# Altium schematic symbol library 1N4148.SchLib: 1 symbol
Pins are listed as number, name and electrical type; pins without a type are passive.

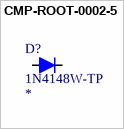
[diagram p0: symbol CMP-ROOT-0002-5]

## CMP-ROOT-0002-5
designator D?, comment 1N4148W-TP
MICRO COMMERCIAL COMPONENTS - 1N4148W-TP - SWITCHING DIODE, 150mA, 100V, SOD123, FU; Value: Single; Value: 4ns; Value: 03011134; Value: 1.2mm; Value: 2A; Value: 1V; Value: Surface Mount; Value: 1.8mm; Value: 4ns; Value: 5uA; Value: DIODE GEN PURP 100V 150MA SOD123; Value: 150°C; Value: Lead Free; Value: MCC; Value: -65°C; Value: Tape and Reel; Value: 2A; Value: 2.85mm; Value: SMD; Value: Standard; Value: 400mW; Value: DIODO 1N 4148 SMD SOD-123; Value: No; Value: 4pF; Value: Unknown; Value: 1A; Value: 3000; Value: 2
footprint SOD123
pins: 1 A, 2 K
